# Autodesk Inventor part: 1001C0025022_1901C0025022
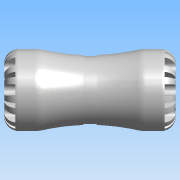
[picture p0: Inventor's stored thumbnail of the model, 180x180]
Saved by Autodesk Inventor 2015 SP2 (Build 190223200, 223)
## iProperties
Created: 2016-12
Part Number: 1001C0025022_1901C0025022
Material: PVC-Piping
Description: PLASSON COPPER PIPE ADAPTOR 25X22 SERIES 1
Document SubType Name: Modeling
Designer: KIM
Mass: 95.2094 g
Surface Area: 200.83 cm^2
Volume: 68.0067 cm^3
Density: 1.4 g/cm^3
Appearance: Smooth - White
ILogicFactory: False
Author: KIM
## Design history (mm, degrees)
derived "1001C.ipt"
feature "Solid1::1001C.ipt"
tag "TaggingFeature1"
body "Solid1"
other parameters: "d1" = 47, "d2" = 48, "d11" = 6.3, "d13" = 6.3, "d14" = 0, "d16" = 360 deg, "d18" = 8 deg, "d19" = 0.5, "d20" = 8 deg, "d21" = 0.5, "d23" = 0, "d25" = 360 deg, "d27" = 18.8, "d28" = 7.5, "d29" = 7.5, "d30" = 12.348, "d31" = 0, "d33" = 0, "d37" = 19.6, "d38" = 0.47, "d44" = 25, "d45" = 19.6, "d46" = 39.95, "d47" = 47, "d50" = 360 deg, "d54" = 0.513, "d60" = 22, "d61" = 31.25, "d62" = 47, "d63" = 19.6, "d64" = 98, "d65" = 48, "d66" = 1.83333, "d67" = 49, "d70" = 6.3, "d72" = 6.3, "d73" = 0, "d75" = 360 deg, "d77" = 8 deg, "d78" = 8 deg, "d79" = 0.5, "d80" = 0.5, "d82" = 0, "d84" = 360 deg, "d87" = 31.25, "d_" = 25, "E_" = 47, "H_" = 98, "l_" = 48, "d_1" = 22, "E_1" = 47, "l_1" = 48, "d12" = 31.25, "d42" = 47, "d52" = 7.875, "d68" = 47, "d69" = 31.25, "d71" = 7.875
